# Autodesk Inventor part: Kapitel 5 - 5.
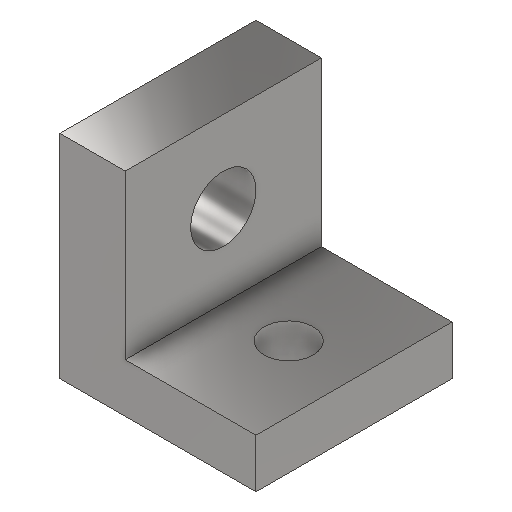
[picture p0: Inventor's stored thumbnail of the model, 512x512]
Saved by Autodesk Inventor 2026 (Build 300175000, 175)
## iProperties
Created: 2022-01
Part Number: Kapitel 5 - 5.
Material: Steel, Mild
Document SubType Name: Modeling
Designer: Lars Bertram Pedersen
Density: 7.85 g/cm^3
Appearance: Semi-Polished
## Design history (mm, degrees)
sketch "Sketch2"
  geometry: L1 (0, 0)-(0, 65); L2 (0, 65)-(20, 65); L3 (20, 65)-(20, 15); L4 (20, 15)-(60, 15); L5 (60, 15)-(60, 0); L6 (60, 0)-(0, 0)
  constraints: 12 end point, 5 perpendicular, 1 vertical
  dimensions: "d4" = 50 distance of L2.end L3.end; "d5" = 15 distance of L4.end L5.end; "d6" = 20 distance of L1.end L2.end; "d7" = 60 distance of L5.end L1.start
extrude "Extrusion1" new body sketch "Sketch2" distance "d8" = 60; taper "d9" = 0 deg
sketch "Sketch3"
  geometry: L1 (0, 0)-(0, -60) reference; L2 (40, 0)-(40, -60) reference; C1 r 7.5 at (20, -30); 2 further points
  constraints: 1 centre point, 1 horizontal alignment, 1 midpoint
  dimensions: "d10" = 20 distance from line of C1.centre L1; "d11" = 15 diameter of C1
extrude "Extrusion2" cut sketch "Sketch3" extent not by distance; stored distance "d12" = 60; taper "d13" = 0 deg
sketch "Sketch4"
  geometry: L1 (0, 50)-(-60, 50) reference; L2 (0, 0)-(-60, 0) reference; C1 r 10 at (-30, 25); 2 further points
  constraints: 1 centre point, 1 midpoint, 1 vertical alignment
  dimensions: "d14" = 25 distance from line of L2 C1.centre; "d15" = 20 diameter of C1
extrude "Extrusion3" cut sketch "Sketch4" extent not by distance; stored distance "d16" = 10; taper "d17" = 0 deg
body "Solid1"
sketch "Sketch1"
  geometry: L1 (0, 0)-(0, 26); L2 (0, 26)-(40, 26); L3 (40, 26)-(40, 10); L4 (40, 10)-(60, 10); L5 (60, 10)-(60, 0); L6 (60, 0)-(0, 0)
  constraints: 12 end point, 5 perpendicular, 1 vertical
  dimensions: "d0" = 60 distance of L5.end L1.start; "d1" = 40 distance of L1.end L2.end; "d2" = 16 distance of L2.end L3.end; "d3" = 10 distance of L4.end L5.end
